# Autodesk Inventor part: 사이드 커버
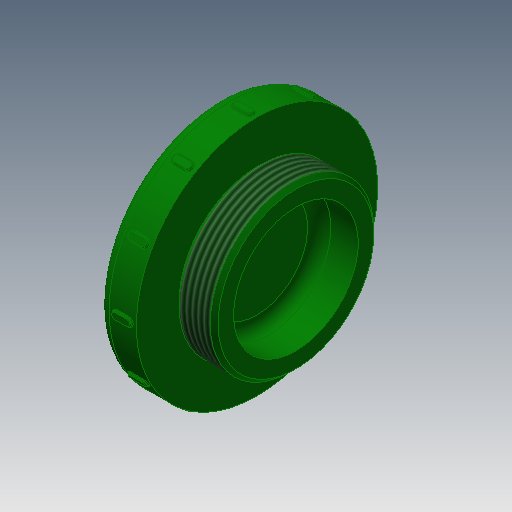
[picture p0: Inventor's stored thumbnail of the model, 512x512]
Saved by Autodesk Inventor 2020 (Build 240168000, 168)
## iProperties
Created: 2016-08
Part Number: 사이드 커버
Material: 스테인리스강
Document SubType Name: Modeling
Designer: mduedu
Density: 8.08 g/cm^3
Appearance: 진녹색
Author: mduedu
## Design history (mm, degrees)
sketch "스케치1"
  geometry: L1 (-5, 0)-(5, 0); L2 (-5, 0)-(-5, 31); L3 (-5, 31)-(5, 31); L4 (5, 31)-(5, 21); L5 (5, 21)-(15, 21); L6 (15, 21)-(15, 16); L7 (15, 16)-(5, 16); L8 (5, 16)-(5, 0); 2 further points
  constraints: 16 end point, 4 parallel, 2 perpendicular, 1 coincident, 1 collinear, 1 horizontal, 1 midpoint, 1 vertical
  dimensions: "d0" = 10 distance of L1.start L1.end; "d2" = 62 diameter of L3 L1; "d3" = 42 diameter of L5 L1; "d4" = 10 distance between parallel lines of L6 L8; "d5" = 5 distance of L5.end L6.end
revolve "회전1" sketch "스케치1" stored, may be unused: angle "d6" = 90 deg
fillet "모깎기1" dims "d7" = 3
sketch "스케치2"
  geometry: L1 (5, -31)-(5, 31) reference; L2 (5, 21)-(15, 21) reference; L3 (0, 0)-(5, 0); L4 (5, 21)-(6, 21); L5 (6, 21)-(6, 20); L6 (6, 20)-(5, 20); L7 (5, 20)-(5, 21)
  constraints: 10 end point, 2 parallel, 1 horizontal, 1 midpoint, 1 perpendicular
  dimensions: "d8" = 1 distance of L2.start L4.end; "d9" = 40 diameter of L6 L3
revolve "회전2" sketch "스케치2" stored, may be unused: angle "d10" = 90 deg
fillet "모깎기2" dims "d11" = 3
feature "스레드1" dims "d12" = 10, "d13" = 0
chamfer "모따기1" distance "d14" = 1; stored, may be unused: second distance "d15" = 2, angle "d16" = 45 deg
node "작업 평면1"
sketch "스케치3"
  geometry: L1 (1, -1)-(-4, -1); L2 (-4, -1)-(-4, 1); L3 (-4, 1)-(1, 1); L4 (1, 1)-(1, -1); 2 further points
  constraints: 8 end point, 2 parallel, 1 horizontal, 1 horizontal alignment, 1 midpoint, 1 perpendicular
  dimensions: "d18" = 2 distance of L3.end L1.start; "d20" = 5 distance of L1.start L1.end; "d21" = 1 distance from line of L4 point (0, 0)
extrude "돌출1" join sketch "스케치3" stored distance "d22" = 10; taper "d23" = 0 deg
fillet "모깎기3" dims "d24" = 1
fillet "모깎기4" dims "d25" = 0.2
sketch "스케치4"
  geometry: 2 further points
  constraints: 1 coincident, 1 other
feature "엠보싱1" sketch "스케치4" dims "d0" = 10, "d2" = 62, "d3" = 42, "d4" = 10, "d5" = 5, "d29" = 0.5, "d30" = 0
node "솔리드1"
pattern_circular "원형 패턴1" dims angle "d27" = 360 deg
other parameters: "d17" = 31.5
